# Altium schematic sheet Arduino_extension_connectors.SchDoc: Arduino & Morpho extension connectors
size A4; Date: Not used; ApprovedBy: Not used; CheckedBy: Not used; Author: Not used; CompanyName: STMicroelectronics; DrawnBy: Not used; Engineer: Not used; Organization: Not used; Address1: Not used; Address2: Not used; Address3: Not used; Address4: Not used; DocumentNumber: 5; Revision: Not used; SheetNumber: 5; SheetTotal: 8
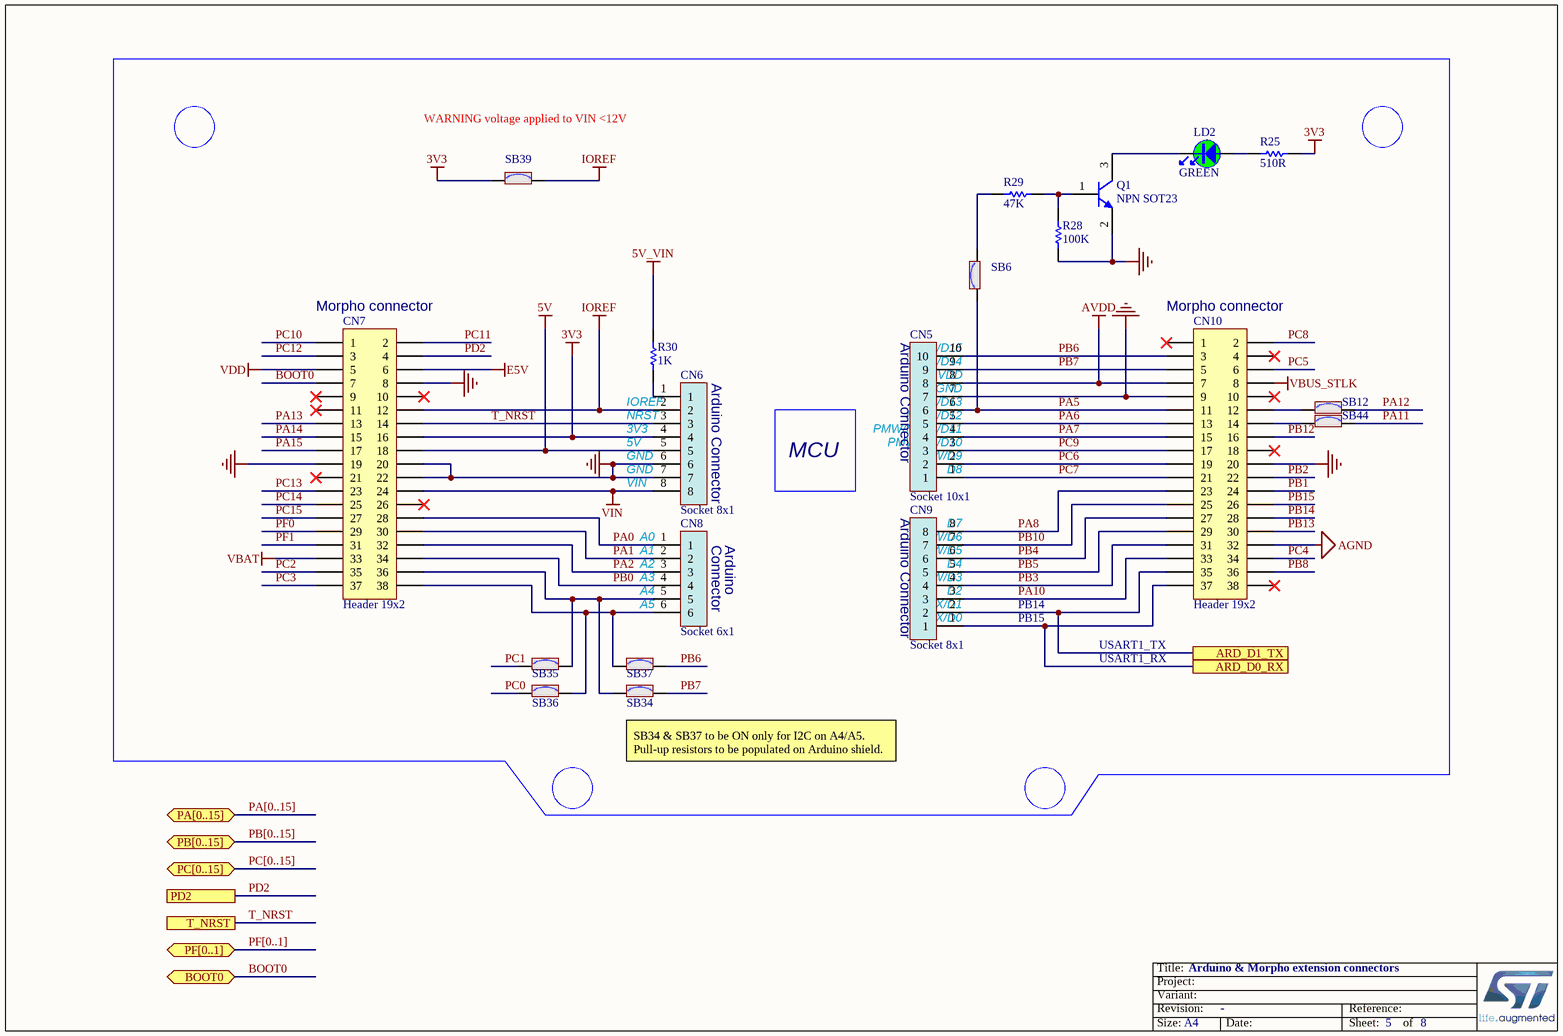
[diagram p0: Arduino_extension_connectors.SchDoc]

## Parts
CN5  Socket 10x1  [CON_SAMTEC_SSQ-110-03-F-S]
CN6  Socket 8x1  [CON_SAMTEC_SSQ-108-03-F-S]
CN7  value Header 19x2  [CON_SAMTEC_TSW-119-09-X-D]
CN8  Socket 6x1  [CON_SAMTEC_SSQ-106-03-F-S]
CN9  Socket 8x1  [CON_SAMTEC_SSQ-108-03-F-S]
CN10  value Header 19x2  [CON_SAMTEC_TSW-119-09-X-D]
LD2  value GREEN  [LED_0603_OSRAM_LG-Q396-PS-35_GREEN_1A2K_H0P4]  (hidden comment: LED_green)
Q1  value NPN SOT23  [NPN_SOT23]
R25  value 510R  [R0603]
R28  value 100K  [R0603]
R29  value 47K  [R0603]
R30  value 1K  [R0603]
SB6  (no value)  [SOLDER-BRIDGE_R0603-0R]
SB12  (no value)  [SOLDER-BRIDGE_R0603-0R]
SB34  (no value)  [SOLDER-BRIDGE_R0603-0R]
SB35  (no value)  [SOLDER-BRIDGE_R0603-0R]
SB36  (no value)  [SOLDER-BRIDGE_R0603-0R]
SB37  (no value)  [SOLDER-BRIDGE_R0603-0R]
SB39  (no value)  [SOLDER-BRIDGE_R0603-0R]
SB44  (no value)  [SOLDER-BRIDGE_R0603-0R]

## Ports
ARD_D0_RX, ARD_D1_TX, BOOT0 (bidir), PA[0..15] (bidir), PB[0..15] (bidir), PC[0..15] (bidir), PD2, PF[0..1] (bidir), T_NRST

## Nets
3V3: CN6.4 CN7.16 R25.1 SB39.1
5V: CN6.5 CN7.18
5V_VIN: R30.2
AGND: CN10.32
AVDD: CN5.8 CN10.7
E5V: CN7.6
GND: CN5.7 CN6.6 CN6.7 CN7.8 CN7.19 CN7.20 CN7.22 CN10.9 CN10.20 Q1.2(E) R28.1
IOREF: CN6.2 CN7.12 SB39.2
VBAT: CN7.33
VBUS_STLK: CN10.8
VDD: CN7.5
VIN: CN6.8 CN7.24
ARD_D0_RX: CN9.1 CN10.37 ; port ARD_D0_RX
ARD_D1_TX: CN9.2 CN10.35 ; port ARD_D1_TX
BOOT0: CN7.7 ; port BOOT0
PA0: CN7.28 CN8.1
PA1: CN7.30 CN8.2
PA2: CN7.32 CN8.3
PA5: CN5.6 CN10.11 SB6.1
PA6: CN5.5 CN10.13
PA7: CN5.4 CN10.15
PA8: CN9.8 CN10.23
PA10: CN9.3 CN10.33
PA11: SB44.2
PA12: SB12.2
PA13: CN7.13
PA14: CN7.15
PA15: CN7.17
PB0: CN7.34 CN8.4
PB1: CN10.24
PB2: CN10.22
PB3: CN9.4 CN10.31
PB4: CN9.6 CN10.27
PB5: CN9.5 CN10.29
PB6: CN5.10 CN10.3 SB37.2
PB7: CN5.9 CN10.5 SB34.2
PB8: CN10.36
PB10: CN9.7 CN10.25
PB12: CN10.16
PB13: CN10.30
PB14: CN10.28
PB15: CN10.26
PC0: SB36.1
PC1: SB35.1
PC2: CN7.35
PC3: CN7.37
PC4: CN10.34
PC5: CN10.6
PC6: CN5.2 CN10.19
PC7: CN5.1 CN10.21
PC8: CN10.2
PC9: CN5.3 CN10.17
PC10: CN7.1
PC11: CN7.2
PC12: CN7.3
PC13: CN7.23
PC14: CN7.25
PC15: CN7.27
PD2: CN7.4 ; port PD2
PF0: CN7.29
PF1: CN7.31
T_NRST: CN6.3 CN7.14 ; port T_NRST
NetCN6_1: CN6.1 R30.1
NetCN7_36: CN7.36 CN8.5 SB34.1 SB35.2
NetCN7_38: CN7.38 CN8.6 SB36.2 SB37.1
NetCN10_12: CN10.12 SB12.1
NetCN10_14: CN10.14 SB44.1
NetLD2_1: LD2.1 R25.2
NetLD2_2: LD2.2 Q1.3(C)
NetQ1_1: Q1.1(B) R28.2 R29.2
NetR29_1: R29.1 SB6.2

Not connected (* = marked no-connect by the designer): CN7 9* 10* 11* 21* 26*; CN10 1* 4* 10* 18* 38*

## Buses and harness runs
bus PA[0..15] = port PA[0..15]
bus PB[0..15] = port PB[0..15]
bus PC[0..15] = port PC[0..15]
bus PF[0..1] = port PF[0..1]

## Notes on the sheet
- WARNING voltage applied to VIN <12V
- (near CN7) Morpho connector
- (near CN10) Morpho connector
- (near CN6) Arduino Connector
- (near CN5) Arduino Connector
- (near CN5) SDA/D14
- (near CN5) SCL/D15
- (near CN5) AVDD
- (near CN6) 5V
- 3V3
- NRST
- IOREF
- (near CN5) PMW/CS/D10
- (near CN5) SCK/D13
- (near CN5) MISO/D12
- (near CN5) PMW/MOSI/D11
- (near CN5) GND
- (near CN6) VIN
- (near CN6) GND
- MCU
- (near CN9) Arduino Connector
- (near CN5) D8
- (near CN5) PMW/D9
- (near CN8) A0
- (near CN8) A1
- (near CN8) A2
- (near CN8) A3
- (near CN8) Connector
- (near CN8) Arduino
- (near CN9) D4
- (near CN9) PMW/D3
- (near CN9) PMW/D5
- (near CN9) PMW/D6
- (near CN9) D7
- (near CN8) A4
- (near CN8) A5
- (near CN9) RX/D0
- (near CN9) TX/D1
- (near CN9) D2
- PB15
- PB14
- USART1_TX
- USART1_RX
- (near SB34) SB34 & SB37 to be ON only for I2C on A4/A5.
  Pull-up resistors to be populated on Arduino shield.

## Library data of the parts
CN5 = MCD-02625: Socket, 10x1, 2.54mm, VR, TH, T=8.51mm/10mm; Part_Type: Connector; Part_Preference: Recommended; Manufacturer: SAMTEC; Manufacturer_Part_Number: SSQ-110-03-F-S; Order_Code_RS: 154-8308; Component_Country_Of_Origin: China, Costa Rica,  Malaysia, Vietnam, USA; ShowFields: YES; ID: 4731
CN6 CN9 = MCD-02624: Socket, 8x1, 2.54mm, VR, TH, T=8.51mm/10mm; Part_Type: Connector; Part_Preference: Recommended; Manufacturer: SAMTEC; Manufacturer_Part_Number: SSQ-108-03-F-S; Order_Code_RS: 180-0395; Component_Country_Of_Origin: China, Costa Rica,  Malaysia, Vietnam, USA; ShowFields: YES; ID: 4730
CN7 CN10 = MCD-00213: Header, 19x2, 2,54mm, VR, TH, Height 5.84mm/10.16mm; Manufacturer_Part_Number: TSW-119-09-x-D; Manufacturer: SAMTEC; Part_Type: Connector; Provided_By: SUBCO
CN8 = MCD-02623: Socket, 6x1, 2.54mm, VR, TH, T=8.51mm/10mm; Part_Type: Connector; Part_Preference: Recommended; Manufacturer: SAMTEC; Manufacturer_Part_Number: SSQ-106-03-F-S; Order_Code_RS: 180-0379; Component_Country_Of_Origin: China, Costa Rica,  Malaysia, Vietnam, USA; ShowFields: YES; ID: 4729
LD2 = MCD-00588: LED Green, 0603 SMD, Forward Voltage Typ=2V, Max=2.5V; Part_Type: Display; Manufacturer_Part_Number: LG Q396-PS-35; Manufacturer: OSRAM OPTO SEMICONDUCTORS; Alternate_Manufacturer_Part_Number: VLMTG1300-GS08; Alternate_Manufacturer: VISHAY SEMICONDUCTOR OPTO DIVISION; Provided_By: SUBCO
Q1 = MCD-00073: NPN Bipolar Transistor; Part_Type: IC; Manufacturer_Part_Number: BSR14; Manufacturer: ON SEMICONDUCTOR; Alternate_Manufacturer_Part_Number: MMBT2222LT1G / MMBT2222ALT1G / MMBT2222ALT3G; ECCN_US: EAR99; ECCN_EU: NEC; Provided_By: SUBCO
R25 = MCD-00225: Resistor,510R,0603,1%,1/10W; Manufacturer_Part_Number: RC0603FR-07510RL; Manufacturer: YAGEO; ECCN_US: EAR99; ECCN_EU: NEC; Provided_By: SUBCO
R28 = MCD-00223: Resistor,100K,0603,1%,1/10W; Manufacturer_Part_Number: RC0603FR-07100KL; Manufacturer: YAGEO; Provided_By: Subcon; Initial_Board_Reference: MB1319
R29 = MCD-00222: Resistor,47K,0603,1%,1/10W; Manufacturer_Part_Number: RC0603FR-0747KL; Manufacturer: YAGEO; ECCN_US: EAR99; ECCN_EU: NEC; Provided_By: SUBCO
R30 = MCD-00070: Resistor,1K,0603,1%,1/10W; Manufacturer_Part_Number: RC0603FR-071KL; Manufacturer: YAGEO; Provided_By: Subcon; Initial_Board_Reference: MB1274
SB6 SB12 SB34-SB37 SB39 SB44 = MCD-00071: Solder Bridge ON; Part_Type: Mechanical; Manufacturer_Part_Number: RC0603JR-070RL; Manufacturer: YAGEO; Provided_By: SUBCO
